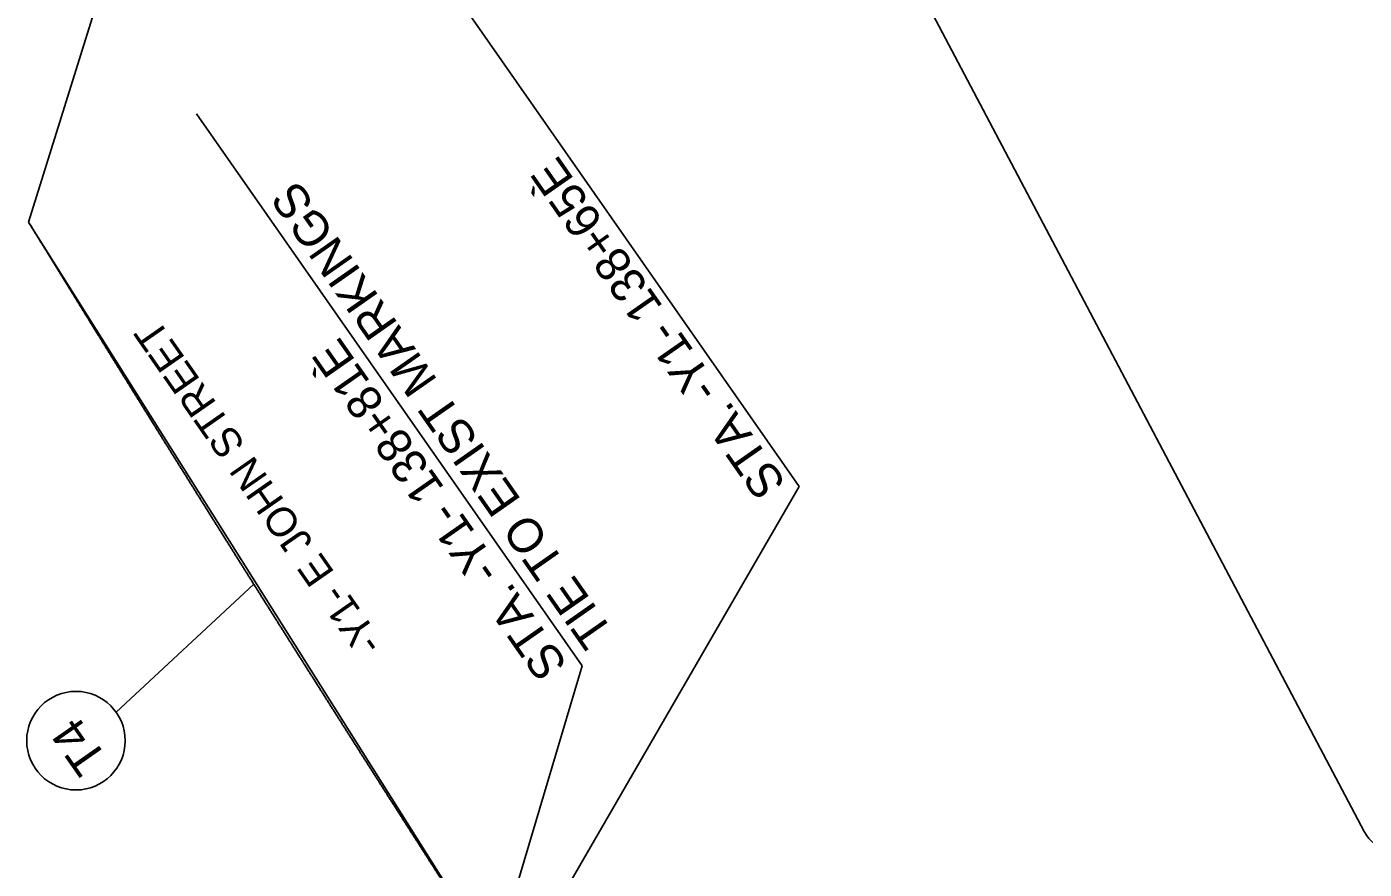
# Model space of a CAD drawing. Extents: x 1487421 to 1489048, y 497792 to 499463.
# Drawn here: x 1487484.7 to 1487756.3, y 498596.8 to 498767.8 of the extents above; entities that cross this region are included whole.
import ezdxf

# ---------------------------------------------------------------- set-up
doc = ezdxf.new("R2010")
doc.units = 0
for name, color, linetype in [('Prop Horizontal Alignment Direction Label', 7, 'Continuous'), ('Prop Mkg 3ft Min Skp 9ft White', 7, 'Continuous'), ('Prop Mkr CR 80ft Spc', 7, 'Continuous'), ('Sheet Title CELL', 7, 'Continuous'), ('Text', 7, 'Continuous')]:
    doc.layers.add(name, color=color, linetype=linetype)

msp = doc.modelspace()

# ---------------------------------------------------------------- linework, layer by layer
at = {"layer": 'Prop Mkg 3ft Min Skp 9ft White'}
for points in [[(1487517.22, 498676.27), (1487516.79, 498676.97), (1487516.35, 498677.67), (1487515.91, 498678.37), (1487515.47, 498679.07), (1487515.04, 498679.77), (1487514.6, 498680.47), (1487514.16, 498681.17), (1487513.72, 498681.87), (1487513.29, 498682.57), (1487512.85, 498683.27), (1487512.41, 498683.97), (1487511.98, 498684.67), (1487511.54, 498685.37), (1487511.1, 498686.07), (1487510.67, 498686.77), (1487510.23, 498687.48), (1487509.79, 498688.18), (1487509.36, 498688.88), (1487508.92, 498689.58), (1487508.48, 498690.28), (1487508.05, 498690.98), (1487507.61, 498691.68), (1487507.18, 498692.38), (1487506.74, 498693.08), (1487506.3, 498693.78), (1487505.87, 498694.48), (1487505.43, 498695.19), (1487505, 498695.89), (1487504.56, 498696.59), (1487504.13, 498697.29), (1487503.69, 498697.99), (1487503.25, 498698.69), (1487502.82, 498699.39), (1487502.38, 498700.1), (1487501.95, 498700.8), (1487501.51, 498701.5), (1487501.08, 498702.2), (1487500.64, 498702.9), (1487500.21, 498703.6), (1487499.77, 498704.31), (1487499.34, 498705.01), (1487498.9, 498705.71), (1487498.47, 498706.41), (1487498.03, 498707.11), (1487497.6, 498707.81), (1487497.17, 498708.52), (1487496.73, 498709.22), (1487496.3, 498709.92), (1487495.86, 498710.62), (1487495.43, 498711.32), (1487495, 498712.03), (1487494.56, 498712.73), (1487494.13, 498713.43), (1487493.69, 498714.13), (1487493.26, 498714.84), (1487492.83, 498715.54), (1487492.39, 498716.24), (1487491.96, 498716.94), (1487491.53, 498717.65), (1487491.09, 498718.35), (1487490.66, 498719.05), (1487490.23, 498719.75), (1487489.79, 498720.46), (1487489.36, 498721.16), (1487488.93, 498721.86), (1487488.49, 498722.57), (1487488.06, 498723.27), (1487487.63, 498723.97), (1487487.2, 498724.67), (1487486.76, 498725.38), (1487486.33, 498726.08), (1487485.9, 498726.78), (1487485.03, 498728.19)], [(1487549.82, 498624.58), (1487549.37, 498625.28), (1487548.93, 498625.98), (1487548.49, 498626.67), (1487548.05, 498627.37), (1487547.6, 498628.07), (1487547.16, 498628.76), (1487546.72, 498629.46), (1487546.27, 498630.16), (1487545.83, 498630.86), (1487545.39, 498631.55), (1487544.95, 498632.25), (1487544.5, 498632.95), (1487544.06, 498633.65), (1487543.62, 498634.34), (1487543.18, 498635.04), (1487542.74, 498635.74), (1487542.29, 498636.44), (1487541.85, 498637.13), (1487541.41, 498637.83), (1487540.97, 498638.53), (1487540.53, 498639.23), (1487540.09, 498639.92), (1487539.64, 498640.62), (1487539.2, 498641.32), (1487538.76, 498642.02), (1487538.32, 498642.72), (1487537.88, 498643.41), (1487537.44, 498644.11), (1487537, 498644.81), (1487536.56, 498645.51), (1487536.11, 498646.21), (1487535.67, 498646.9), (1487535.23, 498647.6), (1487534.79, 498648.3), (1487534.35, 498649), (1487533.91, 498649.7), (1487533.47, 498650.4), (1487533.03, 498651.09), (1487532.59, 498651.79), (1487532.15, 498652.49), (1487531.71, 498653.19), (1487531.27, 498653.89), (1487530.83, 498654.59), (1487530.39, 498655.29), (1487529.95, 498655.99), (1487529.51, 498656.68), (1487529.07, 498657.38), (1487528.63, 498658.08), (1487528.19, 498658.78), (1487527.75, 498659.48), (1487527.31, 498660.18), (1487526.87, 498660.88), (1487526.43, 498661.58), (1487525.99, 498662.28), (1487525.55, 498662.98), (1487525.12, 498663.67), (1487524.68, 498664.37), (1487524.24, 498665.07), (1487523.8, 498665.77), (1487523.36, 498666.47), (1487522.92, 498667.17), (1487522.48, 498667.87), (1487522.04, 498668.57), (1487521.6, 498669.27), (1487521.17, 498669.97), (1487520.73, 498670.67), (1487520.29, 498671.37), (1487519.85, 498672.07), (1487519.41, 498672.77), (1487518.98, 498673.47), (1487518.54, 498674.17), (1487518.1, 498674.87), (1487517.66, 498675.57), (1487517.22, 498676.27)], [(1487582.81, 498573.14), (1487582.36, 498573.83), (1487581.92, 498574.52), (1487581.47, 498575.22), (1487581.02, 498575.91), (1487580.57, 498576.6), (1487580.12, 498577.3), (1487579.67, 498577.99), (1487579.23, 498578.69), (1487578.78, 498579.38), (1487578.33, 498580.07), (1487577.88, 498580.77), (1487577.44, 498581.46), (1487576.99, 498582.16), (1487576.54, 498582.85), (1487576.09, 498583.55), (1487575.64, 498584.24), (1487575.2, 498584.93), (1487574.75, 498585.63), (1487574.3, 498586.32), (1487573.86, 498587.02), (1487573.41, 498587.71), (1487572.96, 498588.41), (1487572.51, 498589.1), (1487572.07, 498589.8), (1487571.62, 498590.49), (1487571.17, 498591.18), (1487570.73, 498591.88), (1487570.28, 498592.57), (1487569.83, 498593.27), (1487569.39, 498593.96), (1487568.94, 498594.66), (1487568.5, 498595.35), (1487568.05, 498596.05), (1487567.6, 498596.74), (1487567.16, 498597.44), (1487566.71, 498598.13), (1487566.27, 498598.83), (1487565.82, 498599.52), (1487565.37, 498600.22), (1487564.93, 498600.92), (1487564.48, 498601.61), (1487564.04, 498602.31), (1487563.59, 498603), (1487563.15, 498603.7), (1487562.7, 498604.39), (1487562.26, 498605.09), (1487561.81, 498605.78), (1487561.36, 498606.48), (1487560.92, 498607.18), (1487560.47, 498607.87), (1487560.03, 498608.57), (1487559.59, 498609.26), (1487559.14, 498609.96), (1487558.7, 498610.65), (1487558.25, 498611.35), (1487557.81, 498612.05), (1487557.36, 498612.74), (1487556.92, 498613.44), (1487556.47, 498614.14), (1487556.03, 498614.83), (1487555.59, 498615.53), (1487555.14, 498616.22), (1487554.7, 498616.92), (1487554.25, 498617.62), (1487553.81, 498618.31), (1487553.37, 498619.01), (1487552.92, 498619.71), (1487552.48, 498620.4), (1487552.03, 498621.1), (1487551.59, 498621.8), (1487551.15, 498622.49), (1487550.7, 498623.19), (1487550.26, 498623.89), (1487549.82, 498624.58)]]:
    msp.add_spline(points, degree=3, dxfattribs=at)
at = {"layer": 'Prop Mkr CR 80ft Spc'}
msp.add_line((1487485.03, 498728.19), (1487582.81, 498573.14), dxfattribs=at)
at = {"layer": 'Sheet Title CELL'}
msp.add_line((1487756.31, 498604.46), (1487556.71, 498982.47), dxfattribs=at)
msp.add_arc((1487763.54, 498608.28), 8.18, 207.8351, 297.8351, dxfattribs=at)
at = {"layer": 'Text'}
for p, q in [((1487499.6, 498774.97), (1487485.03, 498728.19)), ((1487574.74, 498770.13), (1487641.56, 498674.53)), ((1487519.13, 498750.19), (1487597.46, 498638.13)), ((1487641.56, 498674.53), (1487582.81, 498573.14)), ((1487530.78, 498654.67), (1487502.84, 498628.67)), ((1487597.46, 498638.13), (1487584.2, 498593.51))]:
    msp.add_line(p, q, dxfattribs=at)
msp.add_circle((1487494.66, 498622.91), 10, dxfattribs=at)

# ---------------------------------------------------------------- texts
at = {"layer": 'Prop Horizontal Alignment Direction Label'}
msp.add_text('-Y1- E JOHN STREET', height=6, rotation=124.8687, dxfattribs=at).set_placement((1487557.25, 498642.72))
at = {"layer": 'Text'}
for s, rotation, p in [('STA. -Y1- 138+65È', 124.9554, (1487639.07, 498675.14)), ('TIE TO EXIST MARKINGS', 124.9554, (1487603.99, 498644.86)), ('STA. -Y1- 138+81È', 124.9554, (1487594.67, 498638.35)), ('T4', 124.9556, (1487501.25, 498619.16))]:
    msp.add_text(s, height=7, rotation=rotation, dxfattribs=at).set_placement(p)

doc.saveas('drawing.dxf')
